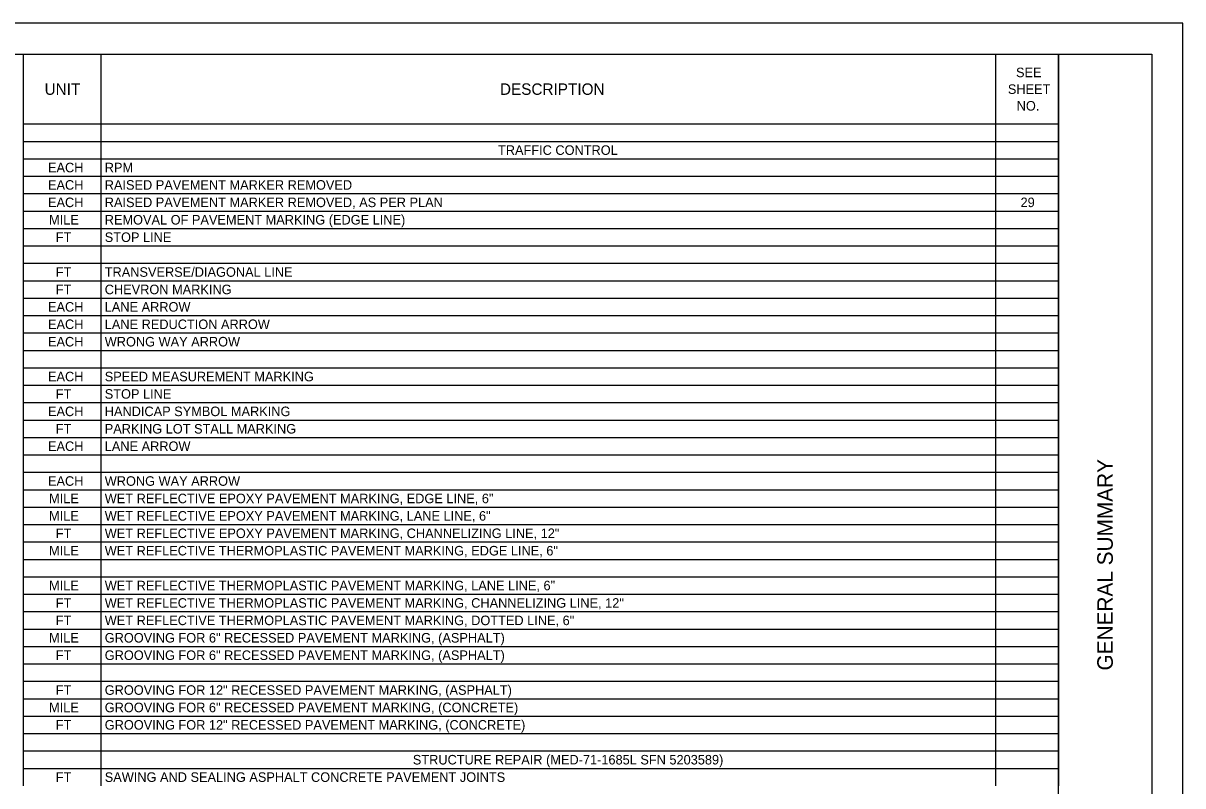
# Model space of a CAD drawing. Extents: x 0 to 34, y 0 to 22.
# Drawn here: x 15.36 to 34, y 9.74 to 22 of the extents above; entities that cross this region are included whole.
import ezdxf

# ---------------------------------------------------------------- set-up
doc = ezdxf.new("R2010")
doc.units = 0
for name, color, linetype in [('SH_Border', 7, 'Continuous'), ('SH_Cut_Line', 7, 'Continuous'), ('SH_Data', 7, 'Continuous'), ('SH_Text', 7, 'Continuous')]:
    doc.layers.add(name, color=color, linetype=linetype)

msp = doc.modelspace()

# ---------------------------------------------------------------- linework, layer by layer
at = {"layer": 'SH_Border'}
msp.add_line((32, 0.5), (32, 21.5), dxfattribs=at)
msp.add_lwpolyline([(1.5, 21.5), (33.5, 21.5), (33.5, 0.5), (1.5, 0.5)], close=True, dxfattribs=at)
at = {"layer": 'SH_Cut_Line'}
msp.add_lwpolyline([(0, 0), (34, 0), (34, 22), (0, 22)], close=True, dxfattribs=at)
at = {"layer": 'SH_Text'}
for p, q in [((15.361, 21.5), (16.607, 21.5)), ((15.361, 21.5), (15.361, 21.22)), ((16.607, 21.5), (30.988, 21.5)), ((16.607, 21.5), (16.607, 21.22)), ((30.988, 21.5), (32, 21.5)), ((30.988, 21.5), (30.988, 21.22)), ((32, 21.5), (32, 21.22)), ((15.361, 21.22), (15.361, 20.94)), ((16.607, 21.22), (16.607, 20.94)), ((30.988, 21.22), (30.988, 20.94)), ((32, 21.22), (32, 20.94)), ((15.361, 20.94), (15.361, 20.66)), ((16.607, 20.94), (16.607, 20.66)), ((30.988, 20.94), (30.988, 20.66)), ((32, 20.94), (32, 20.66)), ((15.361, 20.66), (15.361, 20.38)), ((16.607, 20.66), (16.607, 20.38)), ((30.988, 20.66), (30.988, 20.38)), ((32, 20.66), (32, 20.38)), ((15.361, 20.38), (16.607, 20.38)), ((15.361, 20.38), (15.361, 20.1)), ((16.607, 20.38), (30.988, 20.38)), ((16.607, 20.38), (16.607, 20.1)), ((30.988, 20.38), (32, 20.38)), ((30.988, 20.38), (30.988, 20.1)), ((32, 20.38), (32, 20.1)), ((15.361, 20.1), (16.607, 20.1)), ((15.361, 20.1), (15.361, 18.7)), ((16.607, 20.1), (30.988, 20.1)), ((16.607, 20.1), (16.607, 18.7)), ((30.988, 20.1), (32, 20.1)), ((30.988, 20.1), (30.988, 18.7)), ((32, 20.1), (32, 18.7)), ((15.361, 19.82), (16.607, 19.82)), ((16.607, 19.82), (30.988, 19.82)), ((30.988, 19.82), (32, 19.82)), ((15.361, 19.54), (16.607, 19.54)), ((16.607, 19.54), (30.988, 19.54)), ((30.988, 19.54), (32, 19.54)), ((15.361, 19.26), (16.607, 19.26)), ((16.607, 19.26), (30.988, 19.26)), ((30.988, 19.26), (32, 19.26)), ((15.361, 18.98), (16.607, 18.98)), ((16.607, 18.98), (30.988, 18.98)), ((30.988, 18.98), (32, 18.98)), ((15.361, 18.7), (16.607, 18.7)), ((15.361, 18.7), (15.361, 18.14)), ((16.607, 18.7), (30.988, 18.7)), ((16.607, 18.7), (16.607, 18.14)), ((30.988, 18.7), (32, 18.7)), ((30.988, 18.7), (30.988, 18.14)), ((32, 18.7), (32, 18.14)), ((15.361, 18.42), (16.607, 18.42)), ((16.607, 18.42), (30.988, 18.42)), ((30.988, 18.42), (32, 18.42)), ((15.361, 18.14), (16.607, 18.14)), ((15.361, 18.14), (15.361, 17.86)), ((16.607, 18.14), (30.988, 18.14)), ((16.607, 18.14), (16.607, 17.86)), ((30.988, 18.14), (32, 18.14)), ((30.988, 18.14), (30.988, 17.86)), ((32, 18.14), (32, 17.86)), ((15.361, 17.86), (16.607, 17.86)), ((15.361, 17.86), (15.361, 17.58)), ((16.607, 17.86), (30.988, 17.86)), ((16.607, 17.86), (16.607, 17.58)), ((30.988, 17.86), (32, 17.86)), ((30.988, 17.86), (30.988, 17.58)), ((32, 17.86), (32, 17.58)), ((15.361, 17.58), (16.607, 17.58)), ((15.361, 17.58), (15.361, 17.3)), ((16.607, 17.58), (30.988, 17.58)), ((16.607, 17.58), (16.607, 17.3)), ((30.988, 17.58), (32, 17.58)), ((30.988, 17.58), (30.988, 17.3)), ((32, 17.58), (32, 17.3)), ((15.361, 17.3), (16.607, 17.3)), ((15.361, 17.3), (15.361, 17.02)), ((16.607, 17.3), (30.988, 17.3)), ((16.607, 17.3), (16.607, 17.02)), ((30.988, 17.3), (32, 17.3)), ((30.988, 17.3), (30.988, 17.02)), ((32, 17.3), (32, 17.02)), ((15.361, 17.02), (16.607, 17.02)), ((15.361, 17.02), (15.361, 16.74)), ((16.607, 17.02), (30.988, 17.02)), ((16.607, 17.02), (16.607, 16.74)), ((30.988, 17.02), (32, 17.02)), ((30.988, 17.02), (30.988, 16.74)), ((32, 17.02), (32, 16.74)), ((15.361, 16.74), (16.607, 16.74)), ((15.361, 16.74), (15.361, 16.18)), ((16.607, 16.74), (30.988, 16.74)), ((16.607, 16.74), (16.607, 16.18)), ((30.988, 16.74), (32, 16.74)), ((30.988, 16.74), (30.988, 16.18)), ((32, 16.74), (32, 16.18)), ((15.361, 16.46), (16.607, 16.46)), ((16.607, 16.46), (30.988, 16.46)), ((30.988, 16.46), (32, 16.46)), ((15.361, 16.18), (16.607, 16.18)), ((15.361, 16.18), (15.361, 15.9)), ((16.607, 16.18), (30.988, 16.18)), ((16.607, 16.18), (16.607, 15.9)), ((30.988, 16.18), (32, 16.18)), ((30.988, 16.18), (30.988, 15.9)), ((32, 16.18), (32, 15.9)), ((15.361, 15.9), (16.607, 15.9)), ((15.361, 15.9), (15.361, 15.62)), ((16.607, 15.9), (30.988, 15.9)), ((16.607, 15.9), (16.607, 15.62)), ((30.988, 15.9), (32, 15.9)), ((30.988, 15.9), (30.988, 15.62)), ((32, 15.9), (32, 15.62)), ((15.361, 15.62), (16.607, 15.62)), ((15.361, 15.62), (15.361, 15.34)), ((16.607, 15.62), (30.988, 15.62)), ((16.607, 15.62), (16.607, 15.34)), ((30.988, 15.62), (32, 15.62)), ((30.988, 15.62), (30.988, 15.34)), ((32, 15.62), (32, 15.34)), ((15.361, 15.34), (16.607, 15.34)), ((15.361, 15.34), (15.361, 14.78)), ((16.607, 15.34), (30.988, 15.34)), ((16.607, 15.34), (16.607, 14.78)), ((30.988, 15.34), (32, 15.34)), ((30.988, 15.34), (30.988, 14.78)), ((32, 15.34), (32, 14.78)), ((15.361, 15.06), (16.607, 15.06)), ((16.607, 15.06), (30.988, 15.06)), ((30.988, 15.06), (32, 15.06)), ((15.361, 14.78), (16.607, 14.78)), ((15.361, 14.78), (15.361, 14.5)), ((16.607, 14.78), (30.988, 14.78)), ((16.607, 14.78), (16.607, 14.5)), ((30.988, 14.78), (32, 14.78)), ((30.988, 14.78), (30.988, 14.5)), ((32, 14.78), (32, 14.5)), ((15.361, 14.5), (16.607, 14.5)), ((15.361, 14.5), (15.361, 14.22)), ((16.607, 14.5), (30.988, 14.5)), ((16.607, 14.5), (16.607, 14.22)), ((30.988, 14.5), (32, 14.5)), ((30.988, 14.5), (30.988, 14.22)), ((32, 14.5), (32, 14.22)), ((15.361, 14.22), (16.607, 14.22)), ((15.361, 14.22), (15.361, 13.94)), ((16.607, 14.22), (30.988, 14.22)), ((16.607, 14.22), (16.607, 13.94)), ((30.988, 14.22), (32, 14.22)), ((30.988, 14.22), (30.988, 13.94)), ((32, 14.22), (32, 13.94)), ((15.361, 13.94), (16.607, 13.94)), ((15.361, 13.94), (15.361, 11.7)), ((16.607, 13.94), (30.988, 13.94)), ((16.607, 13.94), (16.607, 11.7)), ((30.988, 13.94), (32, 13.94)), ((30.988, 13.94), (30.988, 11.7)), ((32, 13.94), (32, 11.7)), ((15.361, 13.66), (16.607, 13.66)), ((16.607, 13.66), (30.988, 13.66)), ((30.988, 13.66), (32, 13.66)), ((15.361, 13.38), (16.607, 13.38)), ((16.607, 13.38), (30.988, 13.38)), ((30.988, 13.38), (32, 13.38)), ((15.361, 13.1), (16.607, 13.1)), ((16.607, 13.1), (30.988, 13.1)), ((30.988, 13.1), (32, 13.1)), ((15.361, 12.82), (16.607, 12.82)), ((16.607, 12.82), (30.988, 12.82)), ((30.988, 12.82), (32, 12.82)), ((15.361, 12.54), (16.607, 12.54)), ((16.607, 12.54), (30.988, 12.54)), ((30.988, 12.54), (32, 12.54)), ((15.361, 12.26), (16.607, 12.26)), ((16.607, 12.26), (30.988, 12.26)), ((30.988, 12.26), (32, 12.26)), ((15.361, 11.98), (16.607, 11.98)), ((16.607, 11.98), (30.988, 11.98)), ((30.988, 11.98), (32, 11.98)), ((15.361, 11.7), (16.607, 11.7)), ((15.361, 11.7), (15.361, 11.42)), ((16.607, 11.7), (30.988, 11.7)), ((16.607, 11.7), (16.607, 11.42)), ((30.988, 11.7), (32, 11.7)), ((30.988, 11.7), (30.988, 11.42)), ((32, 11.7), (32, 11.42)), ((15.361, 11.42), (16.607, 11.42)), ((15.361, 11.42), (15.361, 10.3)), ((16.607, 11.42), (30.988, 11.42)), ((16.607, 11.42), (16.607, 10.3)), ((30.988, 11.42), (32, 11.42)), ((30.988, 11.42), (30.988, 10.3)), ((32, 11.42), (32, 10.3)), ((15.361, 11.14), (16.607, 11.14)), ((16.607, 11.14), (30.988, 11.14)), ((30.988, 11.14), (32, 11.14)), ((15.361, 10.86), (16.607, 10.86)), ((16.607, 10.86), (30.988, 10.86)), ((30.988, 10.86), (32, 10.86)), ((15.361, 10.58), (16.607, 10.58)), ((16.607, 10.58), (30.988, 10.58)), ((30.988, 10.58), (32, 10.58)), ((15.361, 10.3), (16.607, 10.3)), ((15.361, 10.3), (15.361, 10.02)), ((16.607, 10.3), (30.988, 10.3)), ((16.607, 10.3), (16.607, 10.02)), ((30.988, 10.3), (32, 10.3)), ((30.988, 10.3), (30.988, 10.02)), ((32, 10.3), (32, 10.02)), ((15.361, 10.02), (16.607, 10.02)), ((15.361, 10.02), (15.361, 9.74)), ((16.607, 10.02), (30.988, 10.02)), ((16.607, 10.02), (16.607, 9.74)), ((30.988, 10.02), (32, 10.02)), ((30.988, 10.02), (30.988, 9.74)), ((32, 10.02), (32, 9.74))]:
    msp.add_line(p, q, dxfattribs=at)

# ---------------------------------------------------------------- texts
at = {"layer": 'SH_Data'}
msp.add_text('GENERAL SUMMARY', height=0.25, rotation=90, dxfattribs=at).set_placement((32.875, 11.594))
at = {"layer": 'SH_Text'}
for s, height, p in [('SEE ', 0.1533, (31.319, 21.132)), ('UNIT', 0.184, (15.705, 20.848)), ('DESCRIPTION', 0.184, (23.024, 20.848)), ('SHEET ', 0.1533, (31.188, 20.863)), ('NO.', 0.1533, (31.33, 20.595)), ('TRAFFIC CONTROL', 0.15333, (22.993, 19.883)), ('EACH', 0.1533, (15.76, 19.603)), ('RPM', 0.1533, (16.672, 19.603)), ('EACH', 0.1533, (15.76, 19.323)), ('RAISED PAVEMENT MARKER REMOVED', 0.15333, (16.672, 19.323)), ('EACH', 0.1533, (15.76, 19.043)), ('RAISED PAVEMENT MARKER REMOVED, AS PER PLAN', 0.15333, (16.672, 19.043)), ('29', 0.1533, (31.392, 19.043)), ('MILE', 0.1533, (15.777, 18.763)), ('REMOVAL OF PAVEMENT MARKING (EDGE LINE)', 0.15333, (16.672, 18.763)), ('STOP LINE', 0.1533, (16.672, 18.483)), ('FT', 0.1533, (15.885, 18.483)), ('TRANSVERSE/DIAGONAL LINE', 0.15333, (16.672, 17.923)), ('FT', 0.1533, (15.885, 17.923)), ('FT', 0.1533, (15.885, 17.643)), ('CHEVRON MARKING', 0.15333, (16.672, 17.643)), ('EACH', 0.1533, (15.76, 17.363)), ('LANE ARROW', 0.1533, (16.672, 17.363)), ('EACH', 0.1533, (15.76, 17.083)), ('LANE REDUCTION ARROW', 0.15333, (16.672, 17.083)), ('EACH', 0.1533, (15.76, 16.803)), ('WRONG WAY ARROW', 0.15333, (16.672, 16.803)), ('EACH', 0.1533, (15.76, 16.243)), ('SPEED MEASUREMENT MARKING', 0.15333, (16.672, 16.243)), ('FT', 0.1533, (15.885, 15.963)), ('STOP LINE', 0.1533, (16.672, 15.963)), ('EACH', 0.1533, (15.76, 15.683)), ('HANDICAP SYMBOL MARKING', 0.15333, (16.672, 15.683)), ('FT', 0.1533, (15.885, 15.403)), ('PARKING LOT STALL MARKING', 0.15333, (16.672, 15.403)), ('EACH', 0.1533, (15.76, 15.123)), ('LANE ARROW', 0.1533, (16.672, 15.123)), ('EACH', 0.1533, (15.76, 14.563)), ('WRONG WAY ARROW', 0.15333, (16.672, 14.563)), ('MILE', 0.1533, (15.777, 14.283)), ('WET REFLECTIVE EPOXY PAVEMENT MARKING, EDGE LINE, 6"', 0.15333, (16.672, 14.283)), ('MILE', 0.1533, (15.777, 14.003)), ('WET REFLECTIVE EPOXY PAVEMENT MARKING, LANE LINE, 6"', 0.15333, (16.672, 14.003)), ('FT', 0.1533, (15.885, 13.723)), ('WET REFLECTIVE EPOXY PAVEMENT MARKING, CHANNELIZING LINE, 12"', 0.15333, (16.672, 13.723)), ('MILE', 0.1533, (15.777, 13.443)), ('WET REFLECTIVE THERMOPLASTIC PAVEMENT MARKING, EDGE LINE, 6"', 0.15333, (16.672, 13.443)), ('MILE', 0.1533, (15.777, 12.883)), ('WET REFLECTIVE THERMOPLASTIC PAVEMENT MARKING, LANE LINE, 6"', 0.15333, (16.672, 12.883)), ('FT', 0.1533, (15.885, 12.603)), ('WET REFLECTIVE THERMOPLASTIC PAVEMENT MARKING, CHANNELIZING LINE, 12"', 0.15333, (16.672, 12.603)), ('FT', 0.1533, (15.885, 12.323)), ('WET REFLECTIVE THERMOPLASTIC PAVEMENT MARKING, DOTTED LINE, 6"', 0.15333, (16.672, 12.323)), ('MILE', 0.1533, (15.777, 12.043)), ('GROOVING FOR 6" RECESSED PAVEMENT MARKING, (ASPHALT)', 0.15333, (16.672, 12.043)), ('FT', 0.1533, (15.885, 11.763)), ('GROOVING FOR 6" RECESSED PAVEMENT MARKING, (ASPHALT)', 0.15333, (16.672, 11.763)), ('FT', 0.1533, (15.885, 11.203)), ('GROOVING FOR 12" RECESSED PAVEMENT MARKING, (ASPHALT)', 0.15333, (16.672, 11.203)), ('MILE', 0.1533, (15.777, 10.923)), ('GROOVING FOR 6" RECESSED PAVEMENT MARKING, (CONCRETE)', 0.15333, (16.672, 10.923)), ('FT', 0.1533, (15.885, 10.643)), ('GROOVING FOR 12" RECESSED PAVEMENT MARKING, (CONCRETE)', 0.15333, (16.672, 10.643)), ('STRUCTURE REPAIR (MED-71-1685L SFN 5203589)', 0.15333, (21.624, 10.083)), ('FT', 0.1533, (15.885, 9.803)), ('SAWING AND SEALING ASPHALT CONCRETE PAVEMENT JOINTS', 0.15333, (16.672, 9.803))]:
    msp.add_text(s, height=height, dxfattribs=at).set_placement(p)

doc.saveas('drawing.dxf')
